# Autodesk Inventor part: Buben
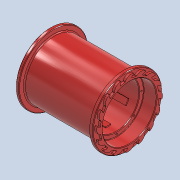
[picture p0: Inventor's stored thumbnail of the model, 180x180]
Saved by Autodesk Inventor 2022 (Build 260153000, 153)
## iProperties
Created: 2025-05
Part Number: Buben
Material: Všeobecné
Document SubType Name: Modeling
Designer: jbart
Density: 1 g/cm^3
Appearance: Oranžovo-červená
Mass: 65127.3 g
Surface Area: 28887.7 cm^2
Volume: 65127.3 cm^3
Author: jbart
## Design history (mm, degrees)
sketch "Náčrt1"
  geometry: L1 (0, 0)-(714, 0); L2 (714, 320)-(714, 250); L3 (714, 250)-(614, 250); L4 (614, 250)-(614, 210); L5 (614, 210)-(355, 210); L6 (355, 210)-(355, 190); L7 (355, 190)-(265, 190); L8 (265, 190)-(265, 205); L9 (265, 205)-(80, 205); L10 (80, 205)-(80, 250); L11 (80, 250)-(0, 250); L12 (0, 250)-(0, 320); L13 (714, 320)-(684, 320); L14 (684, 320)-(684, 270); L15 (0, 320)-(30, 320); L16 (30, 320)-(30, 270); L17 (684, 270)-(30, 270); 5 further points
  constraints: 34 end point, 9 perpendicular, 5 midpoint, 4 horizontal, 3 horizontal alignment, 2 vertical, 2 vertical alignment
  dimensions: "d1" = 420 diameter of L5 L1; "d2" = 259 distance of L4.end L5.end; "d3" = 410 diameter of L9 L1; "d4" = 380 diameter of L7 L1; "d5" = 90 distance of L6.end L7.end; "d6" = 500 diameter of L3 L1; "d7" = 100 distance of L2.end L3.end; "d8" = 185 distance of L8.end L9.end; "d9" = 80 distance of L10.end L11.end; "d11" = 640 diameter of L13 L1; "d12" = 540 diameter of L14.end L1; "d13" = 30 distance of L2.start L13.end; "d14" = 30 distance of L12.end L15.end
revolve "Rotace1" sketch "Náčrt1" stored, may be unused: angle "d15" = 90 deg
node "Pracovní rovina1"
sketch "Náčrt3"
  geometry: L1 (-25, 198)-(25, 198); L2 (0, 0)-(0, 10); L3 (-25, 198)-(-25, 203.47); L4 (25, 198)-(25, 203.47); C1 r 205 at (0, 0) reference; A1 r 205 centre (0, 0) between (-25, 203.47) and (25, 203.47) reference; 1 further point
  constraints: 8 end point, 3 vertical, 2 point on circle, 1 horizontal, 1 symmetric about line
  dimensions: "d17" = 50 distance of L1.start L1.end; "d18" = 198 distance from line of point (0, 0) L1; "d19" = 10 distance of L2.start L2.end
extrude "Vysunutí1" join sketch "Náčrt3" stored distance "d20" = 10; taper "d21" = 0 deg
pattern_circular "Kruhové pole1" dims angle "d23" = 360 deg
node "Pracovní rovina2"
sketch "Náčrt4"
  geometry: L1 (-25, 200)-(25, 200); L2 (0, 0)-(0, 10); L3 (25, 200)-(25, 208.507); L4 (-25, 200)-(-25, 208.507); A1 r 210 centre (0, 0) between (-25, 208.507) and (25, 208.507) reference; 1 further point
  constraints: 8 end point, 2 point on circle, 2 vertical, 1 horizontal, 1 perpendicular, 1 symmetric about line, 2 other
  dimensions: "d26" = 50 distance of L1.start L1.end; "d27" = 10 distance of L2.start L2.end; "d28" = 200 distance from line of point (0, 0) L1
extrude "Vysunutí2" join sketch "Náčrt4" stored distance "d29" = 10; taper "d30" = 0 deg
pattern_circular "Kruhové pole2" dims angle "d32" = 360 deg
sketch "Náčrt5" dims "d34" = 460
  geometry: L1 (0, 0)-(0, 230); 2 further points
  constraints: 2 coincident, 2 end point, 1 vertical, 1 vertical alignment, 2 other
hole "Díra1" sketch "Náčrt5" at (0, 230) diameter "d35" = 13.835; stored, may be unused: countersink angle "d39" = 90 deg, drill point angle "d41" = 118 deg; dims "d36" = 30, "d37" = 4, "d38" = 2, "d40" = 35
pattern_circular "Kruhové pole3" dims angle "d43" = 360 deg
sketch "Náčrt6" dims "d45" = 460
  geometry: L1 (0, 0)-(0, 230); 3 further points
  constraints: 2 coincident, 2 end point, 1 vertical, 1 vertical alignment, 2 other
hole "Díra2" sketch "Náčrt6" at (0, 230) diameter "d46" = 13.835; stored, may be unused: countersink angle "d50" = 90 deg, drill point angle "d52" = 118 deg; dims "d47" = 30, "d48" = 4, "d49" = 2, "d51" = 35
pattern_circular "Kruhové pole4" dims angle "d54" = 360 deg
chamfer "Zkosení1" distance "d56" = 5; stored, may be unused: second distance "d57" = 2, angle "d58" = 45 deg
chamfer "Zkosení2" distance "d59" = 5; stored, may be unused: second distance "d60" = 2, angle "d61" = 45 deg
fillet "Zaoblení1" dims "d62" = 4
sketch "Náčrt7"
  geometry: C1 r 250 at (0, 0); C2 r 305 at (0, 0); A1 r 40 centre (53.96, 256.447) between (35.43, 291.896) and (19.34, 276.484); A2 r 60 centre (14.509, 244.57) between (34.805, 301.033) and (-40.167, 269.28); A3 r 5 centre (33.114, 296.328) between (35.43, 291.896) and (34.805, 301.033); A4 r 5 centre (23.668, 273.98) between (19.34, 276.484) and (23.237, 268.998); A5 r 5 centre (-44.723, 271.339) between (-43.91, 266.405) and (-40.167, 269.28); A6 r 5 centre (-145.156, 233.57) between (-142.517, 229.323) and (-140.159, 233.411); A7 r 60 centre (-80.189, 231.505) between (-83.045, 291.437) and (-140.159, 233.411); A8 r 5 centre (-82.807, 286.443) between (-78.971, 283.236) and (-83.045, 291.437); A9 r 40 centre (-48.286, 257.576) between (-78.971, 283.236) and (-87.938, 262.839); A10 r 5 centre (-82.981, 262.181) between (-87.938, 262.839) and (-81.473, 257.414); A11 r 5 centre (-223.49, 160.241) between (-219.426, 157.328) and (-218.812, 162.007); A12 r 60 centre (-162.678, 183.196) between (-188.251, 237.473) and (-218.812, 162.007); A13 r 5 centre (-186.12, 232.95) between (-181.349, 231.455) and (-188.251, 237.473); A14 r 40 centre (-143.18, 219.491) between (-181.349, 231.455) and (-181.828, 209.179); A15 r 5 centre (-176.997, 210.468) between (-181.828, 209.179) and (-173.779, 206.642); A16 r 5 centre (-267.799, 62.518) between (-262.93, 61.381) and (-264.153, 65.939); A17 r 60 centre (-220.401, 106.997) between (-264.799, 147.356) and (-264.153, 65.939); A18 r 5 centre (-261.099, 143.993) between (-256.119, 144.437) and (-264.799, 147.356); A19 r 40 centre (-216.277, 147.991) between (-256.119, 144.437) and (-248.037, 123.674); A20 r 5 centre (-244.067, 126.714) between (-248.037, 123.674) and (-239.629, 124.41); A21 r 5 centre (-271.339, -44.723) between (-266.405, -43.91) and (-269.28, -40.167); A22 r 60 centre (-244.57, 14.509) between (-301.033, 34.805) and (-269.28, -40.167); A23 r 5 centre (-296.328, 33.114) between (-291.896, 35.43) and (-301.033, 34.805); A24 r 40 centre (-256.447, 53.96) between (-291.896, 35.43) and (-276.484, 19.34); A25 r 5 centre (-273.98, 23.668) between (-276.484, 19.34) and (-268.998, 23.237); A26 r 5 centre (-233.57, -145.156) between (-229.323, -142.517) and (-233.411, -140.159); A27 r 60 centre (-231.505, -80.189) between (-291.437, -83.045) and (-233.411, -140.159); A28 r 5 centre (-286.443, -82.807) between (-283.236, -78.971) and (-291.437, -83.045); A29 r 40 centre (-257.576, -48.286) between (-283.236, -78.971) and (-262.839, -87.938); A30 r 5 centre (-262.181, -82.981) between (-262.839, -87.938) and (-257.414, -81.473); A31 r 5 centre (-160.241, -223.49) between (-157.328, -219.426) and (-162.007, -218.812); A32 r 60 centre (-183.196, -162.678) between (-237.473, -188.251) and (-162.007, -218.812); A33 r 5 centre (-232.95, -186.12) between (-231.455, -181.349) and (-237.473, -188.251); A34 r 40 centre (-219.491, -143.18) between (-231.455, -181.349) and (-209.179, -181.828); A35 r 5 centre (-210.468, -176.997) between (-209.179, -181.828) and (-206.642, -173.779); A36 r 5 centre (-62.518, -267.799) between (-61.381, -262.93) and (-65.939, -264.153); A37 r 60 centre (-106.997, -220.401) between (-147.356, -264.799) and (-65.939, -264.153); A38 r 5 centre (-143.993, -261.099) between (-144.437, -256.119) and (-147.356, -264.799); A39 r 40 centre (-147.991, -216.277) between (-144.437, -256.119) and (-123.674, -248.037); A40 r 5 centre (-126.714, -244.067) between (-123.674, -248.037) and (-124.41, -239.629); A41 r 5 centre (44.723, -271.339) between (43.91, -266.405) and (40.167, -269.28); A42 r 60 centre (-14.509, -244.57) between (-34.805, -301.033) and (40.167, -269.28); A43 r 5 centre (-33.114, -296.328) between (-35.43, -291.896) and (-34.805, -301.033); A44 r 40 centre (-53.96, -256.447) between (-35.43, -291.896) and (-19.34, -276.484); A45 r 5 centre (-23.668, -273.98) between (-19.34, -276.484) and (-23.237, -268.998); A46 r 5 centre (145.156, -233.57) between (142.517, -229.323) and (140.159, -233.411); A47 r 60 centre (80.189, -231.505) between (83.045, -291.437) and (140.159, -233.411); A48 r 5 centre (82.807, -286.443) between (78.971, -283.236) and (83.045, -291.437); A49 r 40 centre (48.286, -257.576) between (78.971, -283.236) and (87.938, -262.839); A50 r 5 centre (82.981, -262.181) between (87.938, -262.839) and (81.473, -257.414); A51 r 5 centre (223.49, -160.241) between (219.426, -157.328) and (218.812, -162.007); A52 r 60 centre (162.678, -183.196) between (188.251, -237.473) and (218.812, -162.007); A53 r 5 centre (186.12, -232.95) between (181.349, -231.455) and (188.251, -237.473); A54 r 40 centre (143.18, -219.491) between (181.349, -231.455) and (181.828, -209.179); A55 r 5 centre (176.997, -210.468) between (181.828, -209.179) and (173.779, -206.642); A56 r 5 centre (267.799, -62.518) between (262.93, -61.381) and (264.153, -65.939); A57 r 60 centre (220.401, -106.997) between (264.799, -147.356) and (264.153, -65.939); A58 r 5 centre (261.099, -143.993) between (256.119, -144.437) and (264.799, -147.356); A59 r 40 centre (216.277, -147.991) between (256.119, -144.437) and (248.037, -123.674); A60 r 5 centre (244.067, -126.714) between (248.037, -123.674) and (239.629, -124.41); A61 r 5 centre (271.339, 44.723) between (266.405, 43.91) and (269.28, 40.167); A62 r 60 centre (244.57, -14.509) between (301.033, -34.805) and (269.28, 40.167); A63 r 5 centre (296.328, -33.114) between (291.896, -35.43) and (301.033, -34.805); A64 r 40 centre (256.447, -53.96) between (291.896, -35.43) and (276.484, -19.34)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; 1 further point
  constraints: 192 point on circle, 98 centre point, 5 tangent, 3 coincident, 257 other
  dimensions: "d64" = 610 diameter of C2; "d70" = 5 radius of A3; "d71" = 40 radius of A1; "d72" = 60 radius of A2; "d73" = 5 radius of A4; "d74" = 5 radius of A5; "d77" = 360 deg dimension on C1.centre A5.centre (derived); "d81" = 500 diameter of C1
extrude "Vysunutí3" join sketch "Náčrt7" distance "d79" = 20; taper "d80" = 0 deg
chamfer "Zkosení3" distance "d82" = 5; stored, may be unused: second distance "d83" = 2, angle "d84" = 45 deg
fillet "Zaoblení2" dims "d85" = 10
node "Těleso1"
node "Promítnutá smyčka1"
node "Promítnutá smyčka2"
